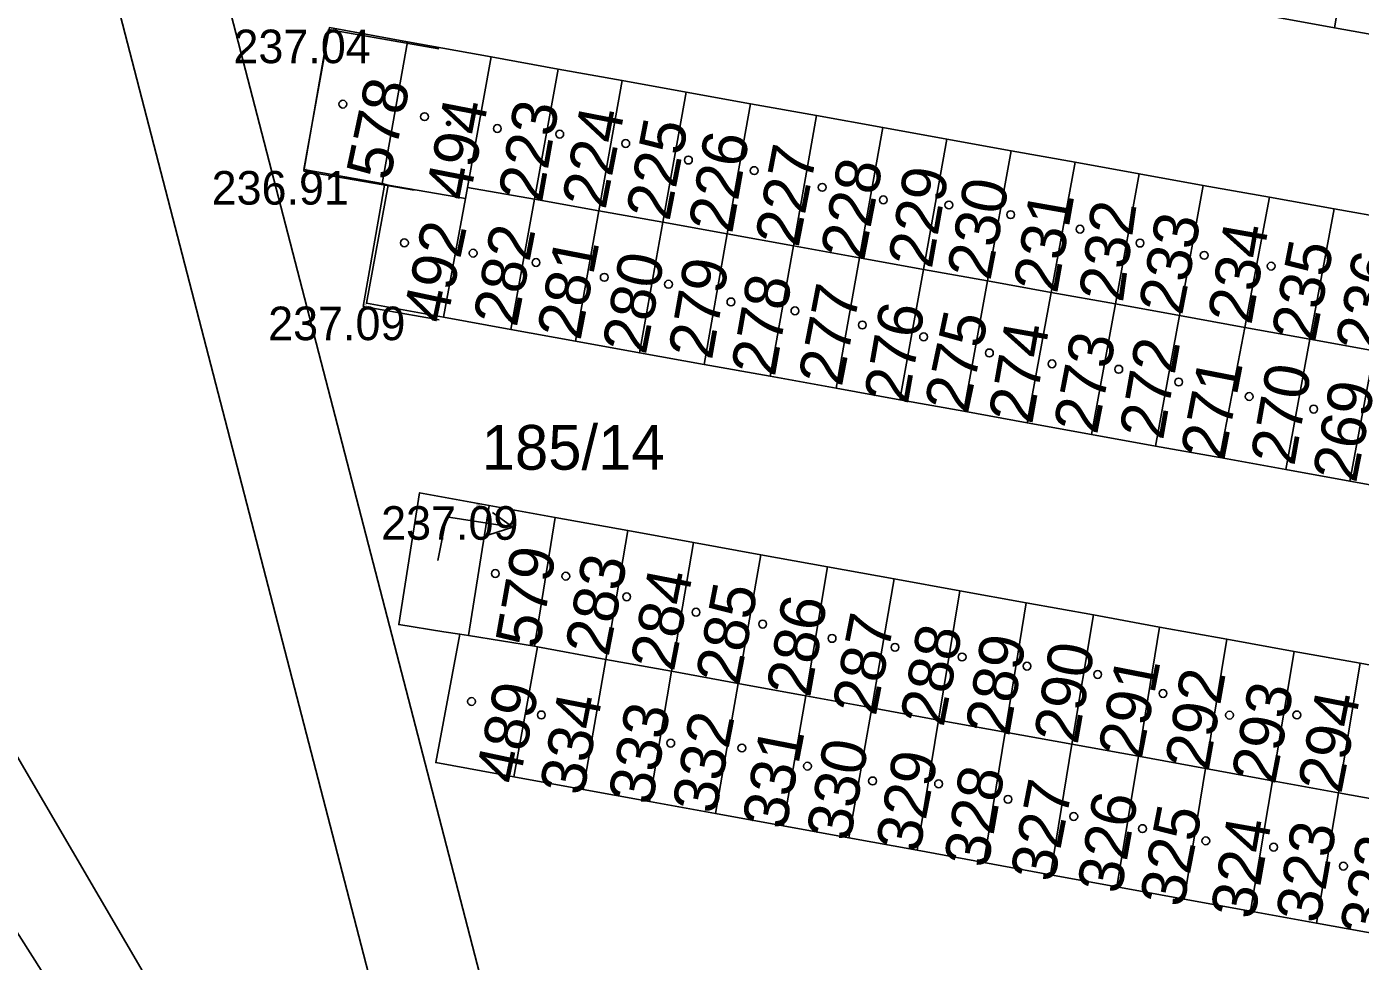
# Model space of a CAD drawing. Extents: x -555757 to -553364, y -1100723 to -1096439.
# Drawn here: x -553939.8 to -553880.2, y -1100666 to -1100624.2 of the extents above; entities that cross this region are included whole.
import ezdxf

# ---------------------------------------------------------------- set-up
doc = ezdxf.new("R2010")
doc.units = 0
for name, color, linetype in [('BUDOVA_ZDENA', 7, 'Continuous'), ('BUDOVY', 7, 'Continuous'), ('C$SLO$PARCELY', 7, 'Continuous'), ('HRANICE$PARCELY', 7, 'Continuous'), ('HRANICE_PARCEL', 7, 'Continuous'), ('OSA$KOLEJI', 7, 'Continuous'), ('PLOTY', 7, 'Continuous'), ('ROZHRANI', 7, 'Continuous'), ('SLOUPY', 7, 'Continuous'), ('VYSKA_PODR_BOD', 7, 'Continuous')]:
    doc.layers.add(name, color=color, linetype=linetype)

# ---------------------------------------------------------------- blocks, each defined once
blk = doc.blocks.new('POINT_DISPLAY')
blk.add_line((0, 0), (0, 0))
blk = doc.blocks.new('4$02')
at = {"layer": 'SLOUPY'}
blk.add_circle((0, 0), 0.175, dxfattribs=at)
blk = doc.blocks.new('1029')
at = {"layer": 'PLOTY'}
for p, q in [((0, 0), (2.964, -0.468)), ((2.964, -0.468), (2.052, 0.182)), ((2.964, -0.468), (1.897, -0.807))]:
    blk.add_line(p, q, dxfattribs=at)
blk = doc.blocks.new('4$021')
at = {"layer": 'BUDOVA_ZDENA'}
for radius in [0.09, 0.0398]:
    blk.add_circle((0, -0.001), radius, dxfattribs=at)

msp = doc.modelspace()

# ---------------------------------------------------------------- linework, layer by layer
at = {"layer": 'BUDOVY'}
for p, q in [((-553927.36, -1100630.64), (-553926.26, -1100624.32)), ((-553921.334, -1100625.177), (-553926.26, -1100624.32)), ((-553922.434, -1100631.497), (-553927.36, -1100630.64)), ((-553923.765, -1100631.266), (-553924.71, -1100636.7)), ((-553921.321, -1100637.289), (-553924.71, -1100636.7))]:
    msp.add_line(p, q, dxfattribs=at)
at = {"layer": 'HRANICE$PARCELY'}
for p, q in [((-553934.48, -1100608.73), (-553905.831, -1100719.27)), ((-553910.795, -1100719.292), (-553938.86, -1100610.94)), ((-553880.27, -1100618.18), (-553881.31, -1100624.24)), ((-553884.17, -1100623.72), (-553881.31, -1100624.24)), ((-553881.31, -1100624.24), (-553878.31, -1100624.78)), ((-553922.73, -1100624.86), (-553923.87, -1100631.2)), ((-553919, -1100625.54), (-553922.73, -1100624.86)), ((-553919, -1100625.54), (-553920.05, -1100631.38)), ((-553916, -1100626.08), (-553919, -1100625.54)), ((-553917.06, -1100631.9), (-553916, -1100626.08)), ((-553913.14, -1100626.59), (-553916, -1100626.08)), ((-553914.18, -1100632.42), (-553913.14, -1100626.59)), ((-553910.28, -1100627.11), (-553913.14, -1100626.59)), ((-553911.32, -1100632.93), (-553910.28, -1100627.11)), ((-553907.41, -1100627.63), (-553910.28, -1100627.11)), ((-553908.45, -1100633.45), (-553907.41, -1100627.63)), ((-553904.45, -1100628.16), (-553907.41, -1100627.63)), ((-553905.49, -1100633.99), (-553904.45, -1100628.16)), ((-553901.49, -1100628.7), (-553904.45, -1100628.16)), ((-553902.54, -1100634.52), (-553901.49, -1100628.7)), ((-553898.63, -1100629.21), (-553901.49, -1100628.7)), ((-553899.68, -1100635.04), (-553898.63, -1100629.21)), ((-553895.76, -1100629.73), (-553898.63, -1100629.21)), ((-553896.82, -1100635.55), (-553895.76, -1100629.73)), ((-553892.9, -1100630.24), (-553895.76, -1100629.73)), ((-553893.97, -1100636.07), (-553892.9, -1100630.24)), ((-553890.04, -1100630.76), (-553892.9, -1100630.24)), ((-553891.1, -1100636.58), (-553890.04, -1100630.76)), ((-553887.18, -1100631.28), (-553890.04, -1100630.76)), ((-553923.87, -1100631.2), (-553923.6, -1100631.27)), ((-553920.14, -1100631.87), (-553923.6, -1100631.27)), ((-553920.05, -1100631.38), (-553920.14, -1100631.87)), ((-553920.05, -1100631.38), (-553917.06, -1100631.9)), ((-553888.24, -1100637.1), (-553887.18, -1100631.28)), ((-553884.22, -1100631.81), (-553887.18, -1100631.28)), ((-553920.14, -1100631.87), (-553921.12, -1100637.17)), ((-553917.06, -1100631.9), (-553918.11, -1100637.72)), ((-553917.06, -1100631.9), (-553914.18, -1100632.42)), ((-553885.32, -1100637.63), (-553884.22, -1100631.81)), ((-553881.32, -1100632.33), (-553884.22, -1100631.81)), ((-553914.18, -1100632.42), (-553915.22, -1100638.24)), ((-553914.18, -1100632.42), (-553911.32, -1100632.93)), ((-553882.41, -1100638.16), (-553881.32, -1100632.33)), ((-553878.44, -1100632.85), (-553881.32, -1100632.33)), ((-553911.32, -1100632.93), (-553912.36, -1100638.76)), ((-553911.32, -1100632.93), (-553908.45, -1100633.45)), ((-553908.45, -1100633.45), (-553909.48, -1100639.28)), ((-553908.45, -1100633.45), (-553905.49, -1100633.99)), ((-553905.49, -1100633.99), (-553906.52, -1100639.81)), ((-553905.49, -1100633.99), (-553902.54, -1100634.52)), ((-553902.54, -1100634.52), (-553903.58, -1100640.34)), ((-553902.54, -1100634.52), (-553899.68, -1100635.04)), ((-553899.68, -1100635.04), (-553900.73, -1100640.86)), ((-553899.68, -1100635.04), (-553896.82, -1100635.55)), ((-553896.82, -1100635.55), (-553897.87, -1100641.38)), ((-553896.82, -1100635.55), (-553893.97, -1100636.07)), ((-553893.97, -1100636.07), (-553895.04, -1100641.89)), ((-553893.97, -1100636.07), (-553891.1, -1100636.58)), ((-553891.1, -1100636.58), (-553892.17, -1100642.41)), ((-553891.1, -1100636.58), (-553888.24, -1100637.1)), ((-553921.12, -1100637.17), (-553918.11, -1100637.72)), ((-553888.24, -1100637.1), (-553889.31, -1100642.93)), ((-553888.24, -1100637.1), (-553885.32, -1100637.63)), ((-553885.32, -1100637.63), (-553886.43, -1100643.45)), ((-553885.32, -1100637.63), (-553882.41, -1100638.16)), ((-553918.11, -1100637.72), (-553915.22, -1100638.24)), ((-553882.41, -1100638.16), (-553883.49, -1100643.98)), ((-553882.41, -1100638.16), (-553879.53, -1100638.67)), ((-553915.22, -1100638.24), (-553912.36, -1100638.76)), ((-553912.36, -1100638.76), (-553909.48, -1100639.28)), ((-553879.53, -1100638.67), (-553880.63, -1100644.5)), ((-553909.48, -1100639.28), (-553906.52, -1100639.81)), ((-553906.52, -1100639.81), (-553903.58, -1100640.34)), ((-553903.58, -1100640.34), (-553900.73, -1100640.86)), ((-553900.73, -1100640.86), (-553897.87, -1100641.38)), ((-553897.87, -1100641.38), (-553895.04, -1100641.89)), ((-553895.04, -1100641.89), (-553892.17, -1100642.41)), ((-553892.17, -1100642.41), (-553889.31, -1100642.93)), ((-553889.31, -1100642.93), (-553886.43, -1100643.45)), ((-553886.43, -1100643.45), (-553883.49, -1100643.98)), ((-553883.49, -1100643.98), (-553880.63, -1100644.5)), ((-553880.63, -1100644.5), (-553877.74, -1100645.02)), ((-553920.01, -1100651.4), (-553919.09, -1100645.59)), ((-553916.14, -1100646.12), (-553919.09, -1100645.59)), ((-553916.14, -1100646.12), (-553917.05, -1100651.87)), ((-553912.88, -1100646.71), (-553916.14, -1100646.12)), ((-553913.87, -1100652.47), (-553912.88, -1100646.71)), ((-553909.95, -1100647.24), (-553912.88, -1100646.71)), ((-553910.93, -1100653), (-553909.95, -1100647.24)), ((-553906.94, -1100647.79), (-553909.95, -1100647.24)), ((-553907.95, -1100653.55), (-553906.94, -1100647.79)), ((-553903.96, -1100648.33), (-553906.94, -1100647.79)), ((-553904.94, -1100654.09), (-553903.96, -1100648.33)), ((-553900.98, -1100648.87), (-553903.96, -1100648.33)), ((-553901.99, -1100654.63), (-553900.98, -1100648.87)), ((-553898.05, -1100649.4), (-553900.98, -1100648.87)), ((-553899, -1100655.18), (-553898.05, -1100649.4)), ((-553895.09, -1100649.94), (-553898.05, -1100649.4)), ((-553896.03, -1100655.72), (-553895.09, -1100649.94)), ((-553892.08, -1100650.48), (-553895.09, -1100649.94)), ((-553893.04, -1100656.26), (-553892.08, -1100650.48)), ((-553889.13, -1100651.02), (-553892.08, -1100650.48)), ((-553920.01, -1100651.4), (-553920.39, -1100651.34)), ((-553890.07, -1100656.8), (-553889.13, -1100651.02)), ((-553886.12, -1100651.56), (-553889.13, -1100651.02)), ((-553917.05, -1100651.87), (-553920.01, -1100651.4)), ((-553916.92, -1100651.91), (-553917.98, -1100657.72)), ((-553917.05, -1100651.87), (-553916.92, -1100651.91)), ((-553916.92, -1100651.91), (-553913.87, -1100652.47)), ((-553887.07, -1100657.35), (-553886.12, -1100651.56)), ((-553883.11, -1100652.11), (-553886.12, -1100651.56)), ((-553913.87, -1100652.47), (-553914.88, -1100658.29)), ((-553913.87, -1100652.47), (-553910.93, -1100653)), ((-553884.08, -1100657.89), (-553883.11, -1100652.11)), ((-553880.16, -1100652.64), (-553883.11, -1100652.11)), ((-553910.93, -1100653), (-553911.92, -1100658.82)), ((-553910.93, -1100653), (-553907.95, -1100653.55)), ((-553881.13, -1100658.43), (-553880.16, -1100652.64)), ((-553876.9, -1100653.23), (-553880.16, -1100652.64)), ((-553907.95, -1100653.55), (-553908.97, -1100659.36)), ((-553907.95, -1100653.55), (-553904.94, -1100654.09)), ((-553904.94, -1100654.09), (-553905.94, -1100659.91)), ((-553904.94, -1100654.09), (-553901.99, -1100654.63)), ((-553901.99, -1100654.63), (-553903.01, -1100660.45)), ((-553901.99, -1100654.63), (-553899, -1100655.18)), ((-553899, -1100655.18), (-553899.96, -1100661)), ((-553899, -1100655.18), (-553896.03, -1100655.72)), ((-553896.03, -1100655.72), (-553896.98, -1100661.55)), ((-553896.03, -1100655.72), (-553893.04, -1100656.26)), ((-553893.04, -1100656.26), (-553894, -1100662.09)), ((-553893.04, -1100656.26), (-553890.07, -1100656.8)), ((-553890.07, -1100656.8), (-553891.03, -1100662.63)), ((-553890.07, -1100656.8), (-553887.07, -1100657.35)), ((-553917.98, -1100657.72), (-553914.88, -1100658.29)), ((-553887.07, -1100657.35), (-553888.02, -1100663.18)), ((-553887.07, -1100657.35), (-553884.08, -1100657.89)), ((-553884.08, -1100657.89), (-553885.06, -1100663.72)), ((-553884.08, -1100657.89), (-553881.13, -1100658.43)), ((-553914.88, -1100658.29), (-553911.92, -1100658.82)), ((-553881.13, -1100658.43), (-553882.12, -1100664.25)), ((-553881.13, -1100658.43), (-553878.01, -1100659)), ((-553911.92, -1100658.82), (-553908.97, -1100659.36)), ((-553908.97, -1100659.36), (-553905.94, -1100659.91)), ((-553905.94, -1100659.91), (-553903.01, -1100660.45)), ((-553903.01, -1100660.45), (-553899.96, -1100661)), ((-553899.96, -1100661), (-553896.98, -1100661.55)), ((-553896.98, -1100661.55), (-553894, -1100662.09)), ((-553894, -1100662.09), (-553891.03, -1100662.63)), ((-553891.03, -1100662.63), (-553888.02, -1100663.18)), ((-553888.02, -1100663.18), (-553885.06, -1100663.72)), ((-553885.06, -1100663.72), (-553882.12, -1100664.25)), ((-553882.12, -1100664.25), (-553879.13, -1100664.8))]:
    msp.add_line(p, q, dxfattribs=at)
for points in [[(-553922.73, -1100624.86), (-553926.22, -1100624.23), (-553927.37, -1100630.57), (-553923.87, -1100631.2)], [(-553923.6, -1100631.27), (-553924.57, -1100636.55), (-553921.12, -1100637.17)], [(-553930.626, -1100719.38), (-553938.92, -1100701.42), (-553936.44, -1100670.56), (-553947.79, -1100652.7), (-553963.47, -1100638.03)], [(-553919.09, -1100645.59), (-553922.19, -1100645.02), (-553923.12, -1100650.91), (-553921.11, -1100651.23), (-553920.39, -1100651.34)], [(-553920.39, -1100651.34), (-553921.47, -1100657.08), (-553917.98, -1100657.72)]]:
    msp.add_lwpolyline(points, dxfattribs=at)
at = {"layer": 'HRANICE_PARCEL'}
msp.add_lwpolyline([(-553962.24, -1100635.46), (-553943.88, -1100650.48), (-553932.83, -1100669.38)], dxfattribs=at)
msp.add_lwpolyline([(-553962.24, -1100635.46), (-553943.88, -1100650.48), (-553932.83, -1100669.38)], dxfattribs=at)
at = {"layer": 'PLOTY'}
msp.add_line((-553921.37, -1100648.04), (-553920.99, -1100646.09), dxfattribs=at)

# ---------------------------------------------------------------- block references
at = {"layer": 'BUDOVA_ZDENA', "xscale": 0.999998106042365, "yscale": 0.9999981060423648, "rotation": -99.87336130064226}
msp.add_blockref('4$021', (-553920.899, -1100628.509), dxfattribs=at)
at = {"layer": 'BUDOVY'}
for p in [(-553925.62, -1100627.65), (-553921.97, -1100628.21), (-553918.72, -1100628.74), (-553915.93, -1100628.99), (-553912.98, -1100629.41), (-553910.18, -1100630.15), (-553907.24, -1100630.62), (-553904.2, -1100631.37), (-553901.47, -1100631.93), (-553898.54, -1100632.16), (-553895.78, -1100632.59), (-553892.68, -1100633.24), (-553922.87, -1100633.85), (-553890, -1100633.86), (-553919.8, -1100634.31), (-553916.99, -1100634.73), (-553887.13, -1100634.41), (-553913.94, -1100635.39), (-553884.14, -1100634.89), (-553911.07, -1100635.7), (-553908.28, -1100636.49), (-553905.42, -1100636.89), (-553902.41, -1100637.52), (-553899.67, -1100638.05), (-553896.73, -1100638.77), (-553893.93, -1100639.26), (-553890.95, -1100639.5), (-553888.27, -1100640.07), (-553885.12, -1100640.72), (-553882.24, -1100641.28), (-553918.81, -1100648.63), (-553915.66, -1100648.75), (-553912.94, -1100649.67), (-553909.84, -1100650.36), (-553906.86, -1100650.89), (-553903.76, -1100651.53), (-553900.95, -1100651.93), (-553897.95, -1100652.36), (-553895.05, -1100652.77), (-553891.89, -1100653.14), (-553919.87, -1100654.35), (-553888.97, -1100653.99), (-553916.75, -1100654.95), (-553886, -1100654.96), (-553882.99, -1100654.95), (-553910.97, -1100656.21), (-553907.79, -1100656.43), (-553904.86, -1100657.24), (-553901.95, -1100657.9), (-553899, -1100658.03), (-553895.9, -1100658.72), (-553892.96, -1100659.49), (-553889.89, -1100660.03), (-553887.06, -1100660.58), (-553884.03, -1100660.86), (-553880.91, -1100661.71)]:
    msp.add_blockref('4$02', p, dxfattribs=at)
at = {"layer": 'PLOTY'}
msp.add_blockref('1029', (-553920.99, -1100646.09), dxfattribs=at)
at = {"layer": 'ROZHRANI'}
for p in [(-553926.26, -1100624.32), (-553927.36, -1100630.64), (-553924.71, -1100636.7), (-553919.66, -1100645.62)]:
    msp.add_blockref('POINT_DISPLAY', p, dxfattribs=at)

# ---------------------------------------------------------------- texts
at = {"layer": 'C$SLO$PARCELY'}
for s, rotation, p in [('578', 78, (-553923.537, -1100631.119)), ('494', 79, (-553919.978, -1100632.028)), ('223', 80, (-553916.726, -1100632.092)), ('224', 79, (-553913.888, -1100632.4)), ('225', 79, (-553911.03, -1100632.921)), ('226', 80, (-553908.227, -1100633.478)), ('227', 79, (-553905.263, -1100634.097)), ('228', 79, (-553902.335, -1100634.695)), ('229', 80, (-553899.307, -1100635.048)), ('230', 79, (-553896.692, -1100635.579)), ('231', 80, (-553893.707, -1100636.159)), ('232', 82, (-553890.767, -1100636.554)), ('233', 79, (-553888.123, -1100637.134)), ('492', 78, (-553921, -1100637.514)), ('282', 79, (-553917.854, -1100637.659)), ('234', 80, (-553885.026, -1100637.558)), ('281', 79, (-553915.008, -1100638.256)), ('235', 79, (-553882.188, -1100638.352)), ('280', 79, (-553912.09, -1100638.895)), ('279', 80, (-553909.132, -1100639.124)), ('236', 79, (-553879.326, -1100638.84)), ('278', 80, (-553906.32, -1100639.869)), ('277', 79, (-553903.329, -1100640.322)), ('276', 80, (-553900.382, -1100641.114)), ('275', 78, (-553897.698, -1100641.528)), ('274', 80, (-553894.822, -1100642.004)), ('273', 79, (-553891.922, -1100642.461)), ('272', 80, (-553888.973, -1100642.709)), ('271', 79, (-553886.248, -1100643.646)), ('270', 80, (-553883.109, -1100643.864)), ('269', 79, (-553880.349, -1100644.626)), ('579', 80, (-553916.854, -1100652.02)), ('283', 79, (-553913.752, -1100652.389)), ('284', 79, (-553910.834, -1100653.055)), ('285', 79, (-553907.917, -1100653.677)), ('286', 80, (-553904.744, -1100654.213)), ('287', 79, (-553901.809, -1100655.042)), ('288', 79, (-553898.782, -1100655.531)), ('289', 80, (-553895.854, -1100655.953)), ('290', 80, (-553892.794, -1100656.313)), ('291', 79, (-553889.932, -1100656.977)), ('292', 80, (-553886.937, -1100657.488)), ('489', 78, (-553917.767, -1100658.109)), ('293', 79, (-553883.976, -1100658.11)), ('334', 79, (-553914.883, -1100658.606)), ('294', 79, (-553881.009, -1100658.516)), ('333', 79, (-553911.82, -1100659.031)), ('332', 79, (-553908.962, -1100659.431)), ('331', 79, (-553905.836, -1100660.127)), ('330', 79, (-553902.969, -1100660.646)), ('329', 79, (-553899.865, -1100661.157)), ('328', 80, (-553896.811, -1100661.84)), ('327', 79, (-553893.85, -1100662.474)), ('326', 80, (-553890.854, -1100662.995)), ('325', 79, (-553888.067, -1100663.598)), ('324', 80, (-553884.894, -1100664.135)), ('323', 80, (-553881.982, -1100664.319)), ('322', 79, (-553879.134, -1100664.951))]:
    msp.add_text(s, height=2, rotation=rotation, dxfattribs=at).set_placement(p)
msp.add_text('185/14', height=2, dxfattribs=at).set_placement((-553919.42, -1100643.99))
at = {"layer": 'OSA$KOLEJI'}
for s, p in [('31', (-553926.26, -1100624.32)), ('32', (-553927.36, -1100630.64)), ('33', (-553924.71, -1100636.7)), ('34', (-553919.66, -1100645.62))]:
    msp.add_text(s, height=0.1, dxfattribs=at).set_placement(p)
at = {"layer": 'VYSKA_PODR_BOD'}
for s, p in [('237.04', (-553930.51, -1100625.82)), ('236.91', (-553931.485, -1100632.14)), ('237.09', (-553928.96, -1100638.2)), ('237.09', (-553923.91, -1100647.12))]:
    msp.add_text(s, height=1.5, dxfattribs=at).set_placement(p)

doc.saveas('drawing.dxf')
